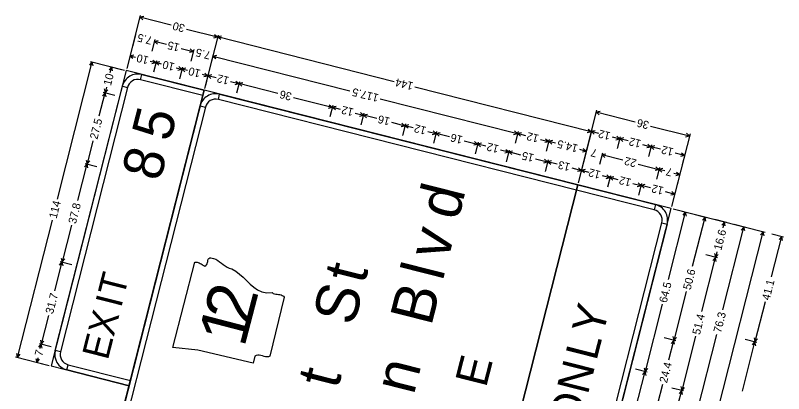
# Model space of a CAD drawing. Extents: x 670002 to 670131, y 737831 to 738002.
# Drawn here: x 670002.43 to 670050.27, y 737877.12 to 737900.71 of the extents above; entities that cross this region are included whole.
import ezdxf

# ---------------------------------------------------------------- set-up
doc = ezdxf.new("R2010")
doc.units = 0
doc.layers.add('R_SIGN', color=7, linetype='Continuous')

msp = doc.modelspace()

# ---------------------------------------------------------------- linework, layer by layer
at = {"layer": 'R_SIGN'}
for p, q in [((670010.212, 737900.707), (670009.369, 737897.383)), ((670010.425, 737900.639), (670010.181, 737900.586)), ((670012.127, 737900.092), (670010.181, 737900.586)), ((670010.37, 737900.423), (670010.181, 737900.586)), ((670013.082, 737899.85), (670015.028, 737899.357)), ((670009.906, 737899.498), (670009.722, 737898.773)), ((670011.117, 737899.191), (670010.933, 737898.466)), ((670011.33, 737899.123), (670011.087, 737899.07)), ((670011.841, 737898.879), (670011.087, 737899.07)), ((670011.275, 737898.907), (670011.087, 737899.07)), ((670015.059, 737899.477), (670014.216, 737896.154)), ((670015.059, 737899.477), (670014.216, 737896.154)), ((670014.784, 737899.303), (670015.028, 737899.357)), ((670014.839, 737899.52), (670015.028, 737899.357)), ((670015.271, 737899.41), (670015.028, 737899.357)), ((670026.011, 737896.571), (670015.028, 737899.357)), ((670015.217, 737899.194), (670015.028, 737899.357)), ((670012.756, 737898.647), (670013.51, 737898.455)), ((670013.321, 737898.618), (670013.51, 737898.455)), ((670009.599, 737898.29), (670009.415, 737897.565)), ((670009.812, 737898.222), (670009.568, 737898.169)), ((670009.92, 737898.08), (670009.568, 737898.169)), ((670009.757, 737898.006), (670009.568, 737898.169)), ((670013.266, 737898.402), (670013.51, 737898.455)), ((670013.54, 737898.576), (670013.357, 737897.851)), ((670013.54, 737898.576), (670013.357, 737897.851)), ((670014.752, 737898.269), (670014.568, 737897.544)), ((670014.752, 737898.269), (670014.568, 737897.544)), ((670014.965, 737898.201), (670014.721, 737898.148)), ((670023.27, 737895.98), (670014.721, 737898.148)), ((670014.91, 737897.985), (670014.721, 737898.148)), ((670005.053, 737889.239), (670007.224, 737897.799)), ((670007.061, 737897.61), (670007.224, 737897.799)), ((670007.103, 737897.83), (670009.218, 737897.293)), ((670007.277, 737897.555), (670007.224, 737897.799)), ((670010.832, 737897.848), (670011.184, 737897.759)), ((670010.94, 737897.706), (670011.184, 737897.759)), ((670010.995, 737897.922), (670011.184, 737897.759)), ((670011.215, 737897.88), (670011.031, 737897.155)), ((670011.427, 737897.812), (670011.184, 737897.759)), ((670011.535, 737897.67), (670011.184, 737897.759)), ((670011.373, 737897.596), (670011.184, 737897.759)), ((670009.339, 737897.263), (670004.668, 737878.846)), ((670008.269, 737897.304), (670008.432, 737897.492)), ((670008.311, 737897.523), (670009.036, 737897.339)), ((670008.343, 737897.141), (670008.432, 737897.492)), ((670008.485, 737897.249), (670008.432, 737897.492)), ((670014.185, 737896.033), (670009.339, 737897.263)), ((670012.448, 737897.439), (670012.799, 737897.349)), ((670012.556, 737897.296), (670012.799, 737897.349)), ((670012.611, 737897.512), (670012.799, 737897.349)), ((670012.83, 737897.47), (670012.646, 737896.745)), ((670012.83, 737897.47), (670012.646, 737896.745)), ((670013.043, 737897.403), (670012.799, 737897.349)), ((670013.151, 737897.26), (670012.799, 737897.349)), ((670012.988, 737897.186), (670012.799, 737897.349)), ((670010.226, 737896.694), (670010.308, 737897.017)), ((670014.063, 737897.029), (670014.415, 737896.94)), ((670014.171, 737896.886), (670014.415, 737896.94)), ((670014.226, 737897.103), (670014.415, 737896.94)), ((670014.446, 737897.06), (670014.262, 737896.335)), ((670014.446, 737897.06), (670014.262, 737896.335)), ((670014.658, 737896.993), (670014.415, 737896.94)), ((670014.929, 737896.809), (670014.415, 737896.94)), ((670014.604, 737896.777), (670014.415, 737896.94)), ((670008.112, 737896.228), (670008.022, 737895.877)), ((670009.093, 737896.293), (670009.416, 737896.211)), ((670015.839, 737896.578), (670016.354, 737896.448)), ((670016.11, 737896.395), (670016.354, 737896.448)), ((670016.165, 737896.611), (670016.354, 737896.448)), ((670016.384, 737896.569), (670016.2, 737895.844)), ((670016.597, 737896.501), (670016.354, 737896.448)), ((670018.78, 737895.833), (670016.354, 737896.448)), ((670016.542, 737896.285), (670016.354, 737896.448)), ((670027.308, 737896.242), (670038.291, 737893.456)), ((670014.185, 737896.033), (670005.089, 737860.169)), ((670007.657, 737894.435), (670008.022, 737895.877)), ((670007.86, 737895.688), (670008.022, 737895.877)), ((670007.902, 737895.908), (670008.627, 737895.724)), ((670007.902, 737895.908), (670008.627, 737895.724)), ((670007.969, 737896.12), (670008.022, 737895.877)), ((670008.185, 737896.066), (670008.022, 737895.877)), ((670008.076, 737895.633), (670008.022, 737895.877)), ((670009.514, 737877.616), (670014.185, 737896.033)), ((670037.449, 737890.133), (670014.185, 737896.033)), ((670015.072, 737895.464), (670015.154, 737895.787)), ((670019.743, 737895.588), (670022.169, 737894.973)), ((670025.155, 737895.502), (670033.704, 737893.334)), ((670013.939, 737895.064), (670014.262, 737894.982)), ((670021.926, 737894.92), (670022.169, 737894.973)), ((670021.981, 737895.136), (670022.169, 737894.973)), ((670022.2, 737895.094), (670022.016, 737894.369)), ((670022.413, 737895.026), (670022.169, 737894.973)), ((670022.684, 737894.842), (670022.169, 737894.973)), ((670022.358, 737894.81), (670022.169, 737894.973)), ((670038.629, 737894.786), (670037.479, 737890.254)), ((670023.594, 737894.612), (670024.108, 737894.481)), ((670023.864, 737894.428), (670024.108, 737894.481)), ((670023.919, 737894.644), (670024.108, 737894.481)), ((670024.139, 737894.602), (670023.955, 737893.877)), ((670024.352, 737894.534), (670024.108, 737894.481)), ((670024.941, 737894.27), (670024.108, 737894.481)), ((670024.297, 737894.318), (670024.108, 737894.481)), ((670038.841, 737894.718), (670038.598, 737894.665)), ((670041.024, 737894.049), (670038.598, 737894.665)), ((670038.787, 737894.502), (670038.598, 737894.665)), ((670025.86, 737894.037), (670026.693, 737893.826)), ((670026.449, 737893.772), (670026.693, 737893.826)), ((670026.504, 737893.989), (670026.693, 737893.826)), ((670026.724, 737893.947), (670026.54, 737893.221)), ((670026.936, 737893.879), (670026.693, 737893.826)), ((670027.207, 737893.695), (670026.693, 737893.826)), ((670026.882, 737893.663), (670026.693, 737893.826)), ((670041.987, 737893.805), (670044.414, 737893.19)), ((670028.117, 737893.464), (670028.631, 737893.334)), ((670028.388, 737893.281), (670028.631, 737893.334)), ((670028.443, 737893.497), (670028.631, 737893.334)), ((670028.662, 737893.455), (670028.478, 737892.73)), ((670028.875, 737893.387), (670028.631, 737893.334)), ((670029.464, 737893.123), (670028.631, 737893.334)), ((670028.82, 737893.171), (670028.631, 737893.334)), ((670033.46, 737893.28), (670033.704, 737893.334)), ((670033.515, 737893.497), (670033.704, 737893.334)), ((670033.734, 737893.455), (670033.55, 737892.729)), ((670033.947, 737893.387), (670033.704, 737893.334)), ((670034.218, 737893.203), (670033.704, 737893.334)), ((670033.893, 737893.171), (670033.704, 737893.334)), ((670038.322, 737893.577), (670037.479, 737890.254)), ((670038.048, 737893.403), (670038.291, 737893.456)), ((670038.103, 737893.619), (670038.291, 737893.456)), ((670038.322, 737893.577), (670038.138, 737892.852)), ((670038.535, 737893.51), (670038.291, 737893.456)), ((670038.772, 737893.335), (670038.291, 737893.456)), ((670038.48, 737893.294), (670038.291, 737893.456)), ((670044.225, 737893.353), (670044.414, 737893.19)), ((670007.264, 737892.884), (670006.898, 737891.442)), ((670030.384, 737892.89), (670031.216, 737892.678)), ((670031.028, 737892.841), (670031.216, 737892.678)), ((670035.128, 737892.973), (670035.642, 737892.842)), ((670035.399, 737892.789), (670035.642, 737892.842)), ((670035.454, 737893.005), (670035.642, 737892.842)), ((670035.673, 737892.963), (670035.489, 737892.238)), ((670035.673, 737892.963), (670035.489, 737892.238)), ((670035.886, 737892.895), (670035.642, 737892.842)), ((670036.065, 737892.735), (670035.642, 737892.842)), ((670035.831, 737892.679), (670035.642, 737892.842)), ((670039.588, 737893.128), (670040.068, 737893.006)), ((670039.825, 737892.953), (670040.068, 737893.006)), ((670039.88, 737893.169), (670040.068, 737893.006)), ((670040.099, 737893.127), (670039.915, 737892.402)), ((670040.312, 737893.059), (670040.068, 737893.006)), ((670040.583, 737892.875), (670040.068, 737893.006)), ((670040.257, 737892.843), (670040.068, 737893.006)), ((670044.444, 737893.311), (670043.295, 737888.779)), ((670044.17, 737893.137), (670044.414, 737893.19)), ((670030.973, 737892.625), (670031.216, 737892.678)), ((670031.247, 737892.799), (670031.063, 737892.074)), ((670031.46, 737892.732), (670031.216, 737892.678)), ((670031.731, 737892.548), (670031.216, 737892.678)), ((670031.405, 737892.516), (670031.216, 737892.678)), ((670037.796, 737892.411), (670037.985, 737892.248)), ((670038.016, 737892.369), (670037.832, 737891.644)), ((670038.016, 737892.369), (670037.832, 737891.644)), ((670041.493, 737892.645), (670042.007, 737892.514)), ((670041.763, 737892.461), (670042.007, 737892.514)), ((670041.818, 737892.677), (670042.007, 737892.514)), ((670042.038, 737892.635), (670041.854, 737891.91)), ((670042.038, 737892.635), (670041.854, 737891.91)), ((670042.251, 737892.567), (670042.007, 737892.514)), ((670042.6, 737892.364), (670042.007, 737892.514)), ((670042.196, 737892.351), (670042.007, 737892.514)), ((670032.641, 737892.317), (670033.155, 737892.187)), ((670032.911, 737892.133), (670033.155, 737892.187)), ((670032.966, 737892.35), (670033.155, 737892.187)), ((670033.186, 737892.308), (670033.002, 737891.583)), ((670033.399, 737892.24), (670033.155, 737892.187)), ((670033.909, 737891.995), (670033.155, 737892.187)), ((670033.344, 737892.024), (670033.155, 737892.187)), ((670037.562, 737892.355), (670037.985, 737892.248)), ((670037.741, 737892.195), (670037.985, 737892.248)), ((670038.985, 737892.123), (670038.801, 737891.398)), ((670039.198, 737892.055), (670038.954, 737892.002)), ((670040.25, 737891.674), (670038.954, 737892.002)), ((670039.143, 737891.839), (670038.954, 737892.002)), ((670043.515, 737892.132), (670044.107, 737891.981)), ((670043.864, 737891.928), (670044.107, 737891.981)), ((670043.918, 737892.144), (670044.107, 737891.981)), ((670044.138, 737892.102), (670043.954, 737891.377)), ((670006.318, 737889.155), (670006.898, 737891.442)), ((670006.735, 737891.254), (670006.898, 737891.442)), ((670006.777, 737891.473), (670007.502, 737891.289)), ((670006.845, 737891.686), (670006.898, 737891.442)), ((670007.061, 737891.631), (670006.898, 737891.442)), ((670006.951, 737891.199), (670006.898, 737891.442)), ((670034.824, 737891.763), (670035.578, 737891.572)), ((670035.335, 737891.519), (670035.578, 737891.572)), ((670035.389, 737891.735), (670035.578, 737891.572)), ((670035.609, 737891.693), (670035.425, 737890.968)), ((670035.609, 737891.693), (670035.425, 737890.968)), ((670035.822, 737891.625), (670035.578, 737891.572)), ((670036.171, 737891.422), (670035.578, 737891.572)), ((670035.767, 737891.409), (670035.578, 737891.572)), ((670041.213, 737891.429), (670042.508, 737891.101)), ((670037.086, 737891.19), (670037.678, 737891.039)), ((670037.435, 737890.986), (670037.678, 737891.039)), ((670037.49, 737891.202), (670037.678, 737891.039)), ((670037.709, 737891.16), (670037.525, 737890.435)), ((670037.709, 737891.16), (670037.525, 737890.435)), ((670037.922, 737891.093), (670037.678, 737891.039)), ((670038.159, 737890.918), (670037.678, 737891.039)), ((670037.867, 737890.877), (670037.678, 737891.039)), ((670042.265, 737891.047), (670042.508, 737891.101)), ((670042.32, 737891.264), (670042.508, 737891.101)), ((670042.539, 737891.222), (670042.355, 737890.496)), ((670042.539, 737891.222), (670042.355, 737890.496)), ((670042.752, 737891.154), (670042.508, 737891.101)), ((670042.867, 737891.01), (670042.508, 737891.101)), ((670042.697, 737890.938), (670042.508, 737891.101)), ((670043.612, 737890.936), (670043.801, 737890.773)), ((670038.975, 737890.711), (670039.455, 737890.589)), ((670039.212, 737890.536), (670039.455, 737890.589)), ((670039.267, 737890.752), (670039.455, 737890.589)), ((670039.486, 737890.71), (670039.302, 737889.985)), ((670039.699, 737890.642), (670039.455, 737890.589)), ((670039.97, 737890.458), (670039.455, 737890.589)), ((670039.644, 737890.426), (670039.455, 737890.589)), ((670043.442, 737890.864), (670043.801, 737890.773)), ((670043.557, 737890.72), (670043.801, 737890.773)), ((670043.831, 737890.894), (670043.647, 737890.169)), ((670028.352, 737854.269), (670037.449, 737890.133)), ((670037.449, 737890.133), (670028.352, 737854.269)), ((670043.264, 737888.658), (670037.449, 737890.133)), ((670040.88, 737890.228), (670041.394, 737890.097)), ((670041.15, 737890.044), (670041.394, 737890.097)), ((670041.205, 737890.26), (670041.394, 737890.097)), ((670041.425, 737890.218), (670041.241, 737889.493)), ((670041.425, 737890.218), (670041.241, 737889.493)), ((670041.638, 737890.15), (670041.394, 737890.097)), ((670041.987, 737889.947), (670041.394, 737890.097)), ((670041.583, 737889.934), (670041.394, 737890.097)), ((670042.902, 737889.715), (670043.494, 737889.564)), ((670043.251, 737889.511), (670043.494, 737889.564)), ((670043.305, 737889.727), (670043.494, 737889.564)), ((670043.525, 737889.685), (670043.341, 737888.96)), ((670034.168, 737852.794), (670043.264, 737888.658)), ((670042.295, 737888.904), (670042.213, 737888.581)), ((670049.125, 737887.172), (670043.385, 737888.627)), ((670044.292, 737888.398), (670043.567, 737888.582)), ((670043.107, 737884.233), (670044.171, 737888.428)), ((670044.008, 737888.24), (670044.171, 737888.428)), ((670044.224, 737888.185), (670044.171, 737888.428)), ((670044.604, 737885.064), (670045.379, 737888.122)), ((670045.5, 737888.091), (670044.775, 737888.275)), ((670045.216, 737887.933), (670045.379, 737888.122)), ((670045.432, 737887.878), (670045.379, 737888.122)), ((670004.724, 737887.942), (670002.553, 737879.382)), ((670005.927, 737887.615), (670005.347, 737885.328)), ((670042.695, 737887.771), (670043.019, 737887.689)), ((670046.708, 737887.785), (670045.983, 737887.969)), ((670046.425, 737887.627), (670046.588, 737887.815)), ((670046.499, 737887.465), (670046.588, 737887.815)), ((670046.641, 737887.572), (670046.588, 737887.815)), ((670047.917, 737887.478), (670047.192, 737887.662)), ((670044.628, 737869.945), (670049.005, 737887.202)), ((670046.489, 737882.355), (670047.796, 737887.509)), ((670047.633, 737887.32), (670047.796, 737887.509)), ((670047.849, 737887.265), (670047.796, 737887.509)), ((670048.842, 737887.014), (670049.005, 737887.202)), ((670049.058, 737886.959), (670049.005, 737887.202)), ((670049.519, 737884.412), (670050.153, 737886.911)), ((670050.273, 737886.88), (670049.548, 737887.064)), ((670049.99, 737886.722), (670050.153, 737886.911)), ((670050.206, 737886.668), (670050.153, 737886.911)), ((670046.15, 737885.581), (670045.425, 737885.765)), ((670046.15, 737885.581), (670045.425, 737885.765)), ((670045.976, 737885.855), (670046.029, 737885.612)), ((670046.118, 737885.962), (670046.029, 737885.612)), ((670046.192, 737885.8), (670046.029, 737885.612)), ((670004.892, 737883.536), (670005.347, 737885.328)), ((670005.184, 737885.139), (670005.347, 737885.328)), ((670005.226, 737885.358), (670005.951, 737885.174)), ((670005.294, 737885.571), (670005.347, 737885.328)), ((670005.51, 737885.516), (670005.347, 737885.328)), ((670005.4, 737885.084), (670005.347, 737885.328)), ((670012.229, 737880.005), (670013.613, 737885.321)), ((670013.613, 737885.321), (670013.681, 737885.321)), ((670013.613, 737885.321), (670013.613, 737885.321)), ((670013.681, 737885.321), (670013.749, 737885.31)), ((670013.749, 737885.31), (670013.813, 737885.291)), ((670013.813, 737885.291), (670013.875, 737885.267)), ((670013.875, 737885.267), (670013.937, 737885.237)), ((670013.937, 737885.237), (670013.996, 737885.205)), ((670013.996, 737885.205), (670014.056, 737885.169)), ((670014.341, 737885.152), (670014.372, 737885.216)), ((670014.372, 737885.216), (670014.392, 737885.288)), ((670014.392, 737885.288), (670014.407, 737885.361)), ((670014.407, 737885.361), (670014.424, 737885.431)), ((670014.424, 737885.431), (670014.448, 737885.494)), ((670014.448, 737885.494), (670014.483, 737885.545)), ((670014.483, 737885.545), (670014.536, 737885.579)), ((670014.536, 737885.579), (670014.611, 737885.589)), ((670014.611, 737885.589), (670014.766, 737885.552)), ((670014.766, 737885.552), (670014.905, 737885.496)), ((670014.905, 737885.496), (670015.033, 737885.425)), ((670015.033, 737885.425), (670015.151, 737885.343)), ((670015.151, 737885.343), (670015.267, 737885.257)), ((670015.267, 737885.257), (670015.381, 737885.17)), ((670045.172, 737882.232), (670046.029, 737885.612)), ((670045.866, 737885.423), (670046.029, 737885.612)), ((670046.082, 737885.368), (670046.029, 737885.612)), ((670014.056, 737885.169), (670014.113, 737885.134)), ((670014.113, 737885.134), (670014.171, 737885.1)), ((670014.171, 737885.1), (670014.229, 737885.068)), ((670014.229, 737885.068), (670014.295, 737885.101)), ((670014.295, 737885.101), (670014.341, 737885.152)), ((670015.381, 737885.17), (670015.499, 737885.086)), ((670015.499, 737885.086), (670015.623, 737885.012)), ((670015.623, 737885.012), (670015.756, 737884.948)), ((670015.756, 737884.948), (670015.904, 737884.903)), ((670015.904, 737884.903), (670016.163, 737884.758)), ((670016.163, 737884.758), (670016.399, 737884.576)), ((670016.399, 737884.576), (670016.621, 737884.373)), ((670016.621, 737884.373), (670016.836, 737884.159)), ((670016.836, 737884.159), (670017.052, 737883.949)), ((670017.052, 737883.949), (670017.277, 737883.756)), ((670017.277, 737883.756), (670017.519, 737883.593)), ((670017.519, 737883.593), (670017.786, 737883.474)), ((670017.786, 737883.474), (670018.085, 737883.41)), ((670018.085, 737883.41), (670018.424, 737883.417)), ((670018.424, 737883.417), (670018.496, 737883.371)), ((670018.496, 737883.371), (670018.575, 737883.341)), ((670018.575, 737883.341), (670018.656, 737883.323)), ((670018.656, 737883.323), (670018.741, 737883.312)), ((670018.741, 737883.312), (670018.825, 737883.303)), ((670018.825, 737883.303), (670018.907, 737883.292)), ((670018.907, 737883.292), (670018.985, 737883.274)), ((670018.985, 737883.274), (670019.056, 737883.244)), ((670044.206, 737883.496), (670043.431, 737880.438)), ((670019.175, 737883.129), (670018.277, 737879.448)), ((670019.056, 737883.244), (670019.121, 737883.198)), ((670019.121, 737883.198), (670019.175, 737883.129)), ((670049.121, 737882.845), (670048.487, 737880.346)), ((670042.715, 737882.688), (670041.651, 737878.493)), ((670004.503, 737881.998), (670004.048, 737880.206)), ((670003.995, 737880.45), (670004.048, 737880.206)), ((670043.551, 737880.408), (670042.826, 737880.592)), ((670043.551, 737880.408), (670042.826, 737880.592)), ((670043.125, 737879.234), (670043.431, 737880.438)), ((670043.268, 737880.25), (670043.431, 737880.438)), ((670043.377, 737880.682), (670043.431, 737880.438)), ((670043.593, 737880.627), (670043.431, 737880.438)), ((670043.484, 737880.195), (670043.431, 737880.438)), ((670044.782, 737880.694), (670043.924, 737877.314)), ((670046.098, 737880.815), (670044.791, 737875.661)), ((670048.608, 737880.315), (670047.883, 737880.499)), ((670048.608, 737880.315), (670047.883, 737880.499)), ((670048.434, 737880.589), (670048.487, 737880.346)), ((670048.65, 737880.534), (670048.487, 737880.346)), ((670003.885, 737880.018), (670004.048, 737880.206)), ((670003.927, 737880.237), (670004.652, 737880.053)), ((670003.977, 737879.925), (670004.048, 737880.206)), ((670004.211, 737880.395), (670004.048, 737880.206)), ((670004.101, 737879.963), (670004.048, 737880.206)), ((670013.797, 737879.837), (670012.229, 737880.005)), ((670047.707, 737877.269), (670048.487, 737880.346)), ((670048.325, 737880.157), (670048.487, 737880.346)), ((670048.541, 737880.102), (670048.487, 737880.346)), ((670002.499, 737879.626), (670002.553, 737879.382)), ((670002.716, 737879.571), (670002.553, 737879.382)), ((670005.237, 737879.733), (670004.913, 737879.815)), ((670017.24, 737879.028), (670013.797, 737879.837)), ((670017.349, 737879.456), (670017.24, 737879.028)), ((670017.434, 737879.501), (670017.349, 737879.456)), ((670017.526, 737879.518), (670017.434, 737879.501)), ((670017.621, 737879.514), (670017.526, 737879.518)), ((670017.721, 737879.496), (670017.621, 737879.514)), ((670017.821, 737879.469), (670017.721, 737879.496)), ((670017.921, 737879.441), (670017.821, 737879.469)), ((670018.277, 737879.448), (670018.197, 737879.416)), ((670002.432, 737879.413), (670004.547, 737878.876)), ((670003.64, 737879.106), (670004.365, 737878.922)), ((670003.708, 737879.319), (670003.761, 737879.075)), ((670003.833, 737879.357), (670003.761, 737879.075)), ((670003.924, 737879.264), (670003.761, 737879.075)), ((670018.017, 737879.418), (670017.921, 737879.441)), ((670018.109, 737879.408), (670018.017, 737879.418)), ((670018.197, 737879.416), (670018.109, 737879.408)), ((670004.668, 737878.846), (670009.514, 737877.616)), ((670005.637, 737878.6), (670005.719, 737878.923)), ((670041.035, 737876.066), (670041.651, 737878.493)), ((670041.772, 737878.462), (670041.047, 737878.646)), ((670041.772, 737878.462), (670041.047, 737878.646)), ((670041.488, 737878.304), (670041.651, 737878.493)), ((670041.598, 737878.736), (670041.651, 737878.493)), ((670041.814, 737878.682), (670041.651, 737878.493)), ((670041.704, 737878.249), (670041.651, 737878.493)), ((670009.514, 737877.616), (670009.514, 737877.616)), ((670042.733, 737877.688), (670042.427, 737876.484)), ((670043.871, 737877.558), (670043.924, 737877.314)), ((670044.045, 737877.284), (670043.32, 737877.468)), ((670043.713, 737876.482), (670043.924, 737877.314)), ((670043.761, 737877.126), (670043.924, 737877.314)), ((670044.087, 737877.503), (670043.924, 737877.314)), ((670043.978, 737877.071), (670043.924, 737877.314))]:
    msp.add_line(p, q, dxfattribs=at)
for points in [[(670014.103, 737895.71), (670010.226, 737896.694), (670010.308, 737897.017), (670014.185, 737896.033), (670014.103, 737895.71)], [(670009.416, 737896.211), (670005.237, 737879.733), (670004.913, 737879.815), (670009.093, 737896.293), (670009.416, 737896.211)], [(670037.367, 737889.81), (670015.072, 737895.464), (670015.154, 737895.787), (670037.449, 737890.133), (670037.367, 737889.81)], [(670014.262, 737894.982), (670005.658, 737861.056), (670005.335, 737861.138), (670013.939, 737895.064), (670014.262, 737894.982)], [(670042.213, 737888.581), (670037.367, 737889.81), (670037.449, 737890.133), (670042.295, 737888.904), (670042.213, 737888.581)], [(670034.091, 737853.845), (670042.695, 737887.771), (670043.019, 737887.689), (670034.414, 737853.763), (670034.091, 737853.845)], [(670005.719, 737878.923), (670009.596, 737877.94), (670009.514, 737877.616), (670005.637, 737878.6), (670005.719, 737878.923)]]:
    msp.add_lwpolyline(points, close=True, dxfattribs=at)
for centre, radius, start, end in [((670010.062, 737896.047), 1, 75.7686, 165.7688), ((670010.062, 737896.047), 0.667, 75.7686, 165.7688), ((670014.909, 737894.818), 1, 75.7686, 165.7688), ((670014.909, 737894.818), 0.667, 75.7686, 165.7688), ((670042.049, 737887.935), 0.667, 345.7686, 75.7688), ((670042.049, 737887.935), 1, 345.7686, 75.7688), ((670005.883, 737879.569), 1, 165.7688, 255.7684), ((670005.883, 737879.569), 0.667, 165.7688, 255.7684)]:
    msp.add_arc(centre, radius, start, end, dxfattribs=at)

# ---------------------------------------------------------------- texts
for s, height, rotation, p in [('30', 0.4987, 165.7688, (670013.023, 737900.122)), ('7.5', 0.4987, 165.7688, (670010.998, 737899.35)), ('15', 0.4987, 165.7688, (670012.696, 737898.919)), ('7.5', 0.4987, 165.7688, (670014.633, 737898.428)), ('10', 0.4987, 165.7688, (670010.773, 737898.121)), ('10', 0.4987, 165.7688, (670012.388, 737897.711)), ('10', 0.4987, 165.7688, (670014.004, 737897.301)), ('10', 0.4987, 75.7686, (670008.384, 737896.288)), ('12', 0.4987, 165.7688, (670015.78, 737896.851)), ('144', 0.4987, 165.7688, (670027.249, 737896.514)), ('36', 0.4987, 165.7688, (670019.683, 737895.861)), ('117.5', 0.4987, 165.7688, (670025.095, 737895.774)), ('5', 2.5, 75.7686, (670012.066, 737892.762)), ('12', 0.4987, 165.7688, (670023.534, 737894.884)), ('16', 0.4987, 165.7688, (670025.801, 737894.309)), ('27.5', 0.4987, 75.7686, (670007.536, 737892.944)), ('12', 0.4987, 165.7688, (670028.058, 737893.737)), ('36', 0.4987, 165.7688, (670041.928, 737894.078)), ('16', 0.4987, 165.7688, (670030.324, 737893.162)), ('12', 0.4987, 165.7688, (670035.068, 737893.245)), ('12', 0.4987, 165.7688, (670039.528, 737893.4)), ('14.5', 0.4987, 165.7688, (670037.503, 737892.628)), ('12', 0.4987, 165.7688, (670041.433, 737892.917)), ('8', 2.5, 75.7686, (670011.439, 737890.291)), ('12', 0.4987, 165.7688, (670032.581, 737892.59)), ('7', 0.499, 165.7688, (670038.7, 737892.324)), ('12', 0.4987, 165.7688, (670043.455, 737892.404)), ('15', 0.4987, 165.7688, (670034.764, 737892.036)), ('13', 0.4987, 165.7688, (670037.026, 737891.462)), ('22', 0.4987, 165.7688, (670041.153, 737891.702)), ('12', 0.4987, 165.7688, (670038.915, 737890.983)), ('7', 0.499, 165.7688, (670043.383, 737891.136)), ('12', 0.4987, 165.7688, (670040.82, 737890.5)), ('d', 2.667, 75.7686, (670029.995, 737887.863)), ('12', 0.4987, 165.7688, (670042.842, 737889.987)), ('114', 0.4987, 75.7686, (670004.996, 737888.001)), ('37.8', 0.4987, 75.7686, (670006.199, 737887.674)), ('v', 2.667, 75.7686, (670029.359, 737885.355)), ('16.6', 0.4987, 75.7686, (670046.39, 737886.022)), ('t', 2.667, 75.7686, (670024.173, 737883.892)), ('l', 2.667, 75.7686, (670029.038, 737884.089)), ('T', 1.667, 75.7686, (670009.181, 737883.083)), ('50.6', 0.4987, 75.7686, (670044.478, 737883.556)), ('2', 3, 75.407, (670017.038, 737881.315)), ('S', 2.667, 75.7686, (670023.511, 737881.281)), ('B', 2.667, 75.7686, (670028.323, 737881.271)), ('64.5', 0.4987, 75.7686, (670042.987, 737882.748)), ('41.1', 0.4987, 75.7686, (670049.394, 737882.904)), ('31.7', 0.4987, 75.7686, (670004.775, 737882.058)), ('I', 1.667, 75.7686, (670009.013, 737882.419)), ('Y', 2, 75.7686, (670039.002, 737880.667)), ('X', 1.667, 75.7686, (670008.556, 737880.617)), ('1', 3, 75.407, (670016.683, 737879.951)), ('51.4', 0.4987, 75.7686, (670045.054, 737880.754)), ('76.3', 0.4987, 75.7686, (670046.371, 737880.875)), ('E', 1.667, 75.7686, (670008.185, 737879.157)), ('L', 2, 75.7686, (670038.609, 737879.116)), ('7', 0.499, 75.7686, (670004.105, 737879.416)), ('E', 2, 75.7686, (670031.737, 737877.445)), ('n', 2.667, 75.7686, (670027.235, 737876.98)), ('N', 2, 75.7686, (670038.073, 737877.003)), ('24.4', 0.4987, 75.7686, (670043.005, 737877.748)), ('t', 2.667, 75.7686, (670022.515, 737877.352)), ('O', 2, 75.7686, (670037.542, 737874.91))]:
    msp.add_text(s, height=height, rotation=rotation, dxfattribs=at).set_placement(p)

doc.saveas('drawing.dxf')
